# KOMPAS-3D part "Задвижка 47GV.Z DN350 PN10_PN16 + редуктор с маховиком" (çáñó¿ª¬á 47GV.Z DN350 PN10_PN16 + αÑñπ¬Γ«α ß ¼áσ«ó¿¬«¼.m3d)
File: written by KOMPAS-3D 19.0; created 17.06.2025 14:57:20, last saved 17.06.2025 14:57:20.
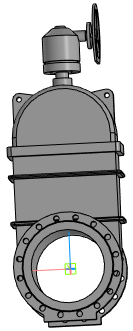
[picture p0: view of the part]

Document properties: Полное имя файла: Задвижка 47GV.Z DN350 PN10_PN16 + редуктор с маховиком.a3d

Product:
- Part/product: Задвижка 47GV.Z DN350 PN10_PN16 + редуктор с маховиком
    Масса: 566.993

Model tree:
1. Операция без истории:1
